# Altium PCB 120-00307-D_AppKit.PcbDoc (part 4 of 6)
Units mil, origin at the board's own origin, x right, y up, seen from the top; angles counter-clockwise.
Board outline 5150 x 3100 mil, 6 copper layers (L1, L2 (GND), L3-SIG, L4-SIG, L5 (PWR), L6), stack 61.956 mil thick; 413 components, 344 nets, 1685 pads, 1021 vias.
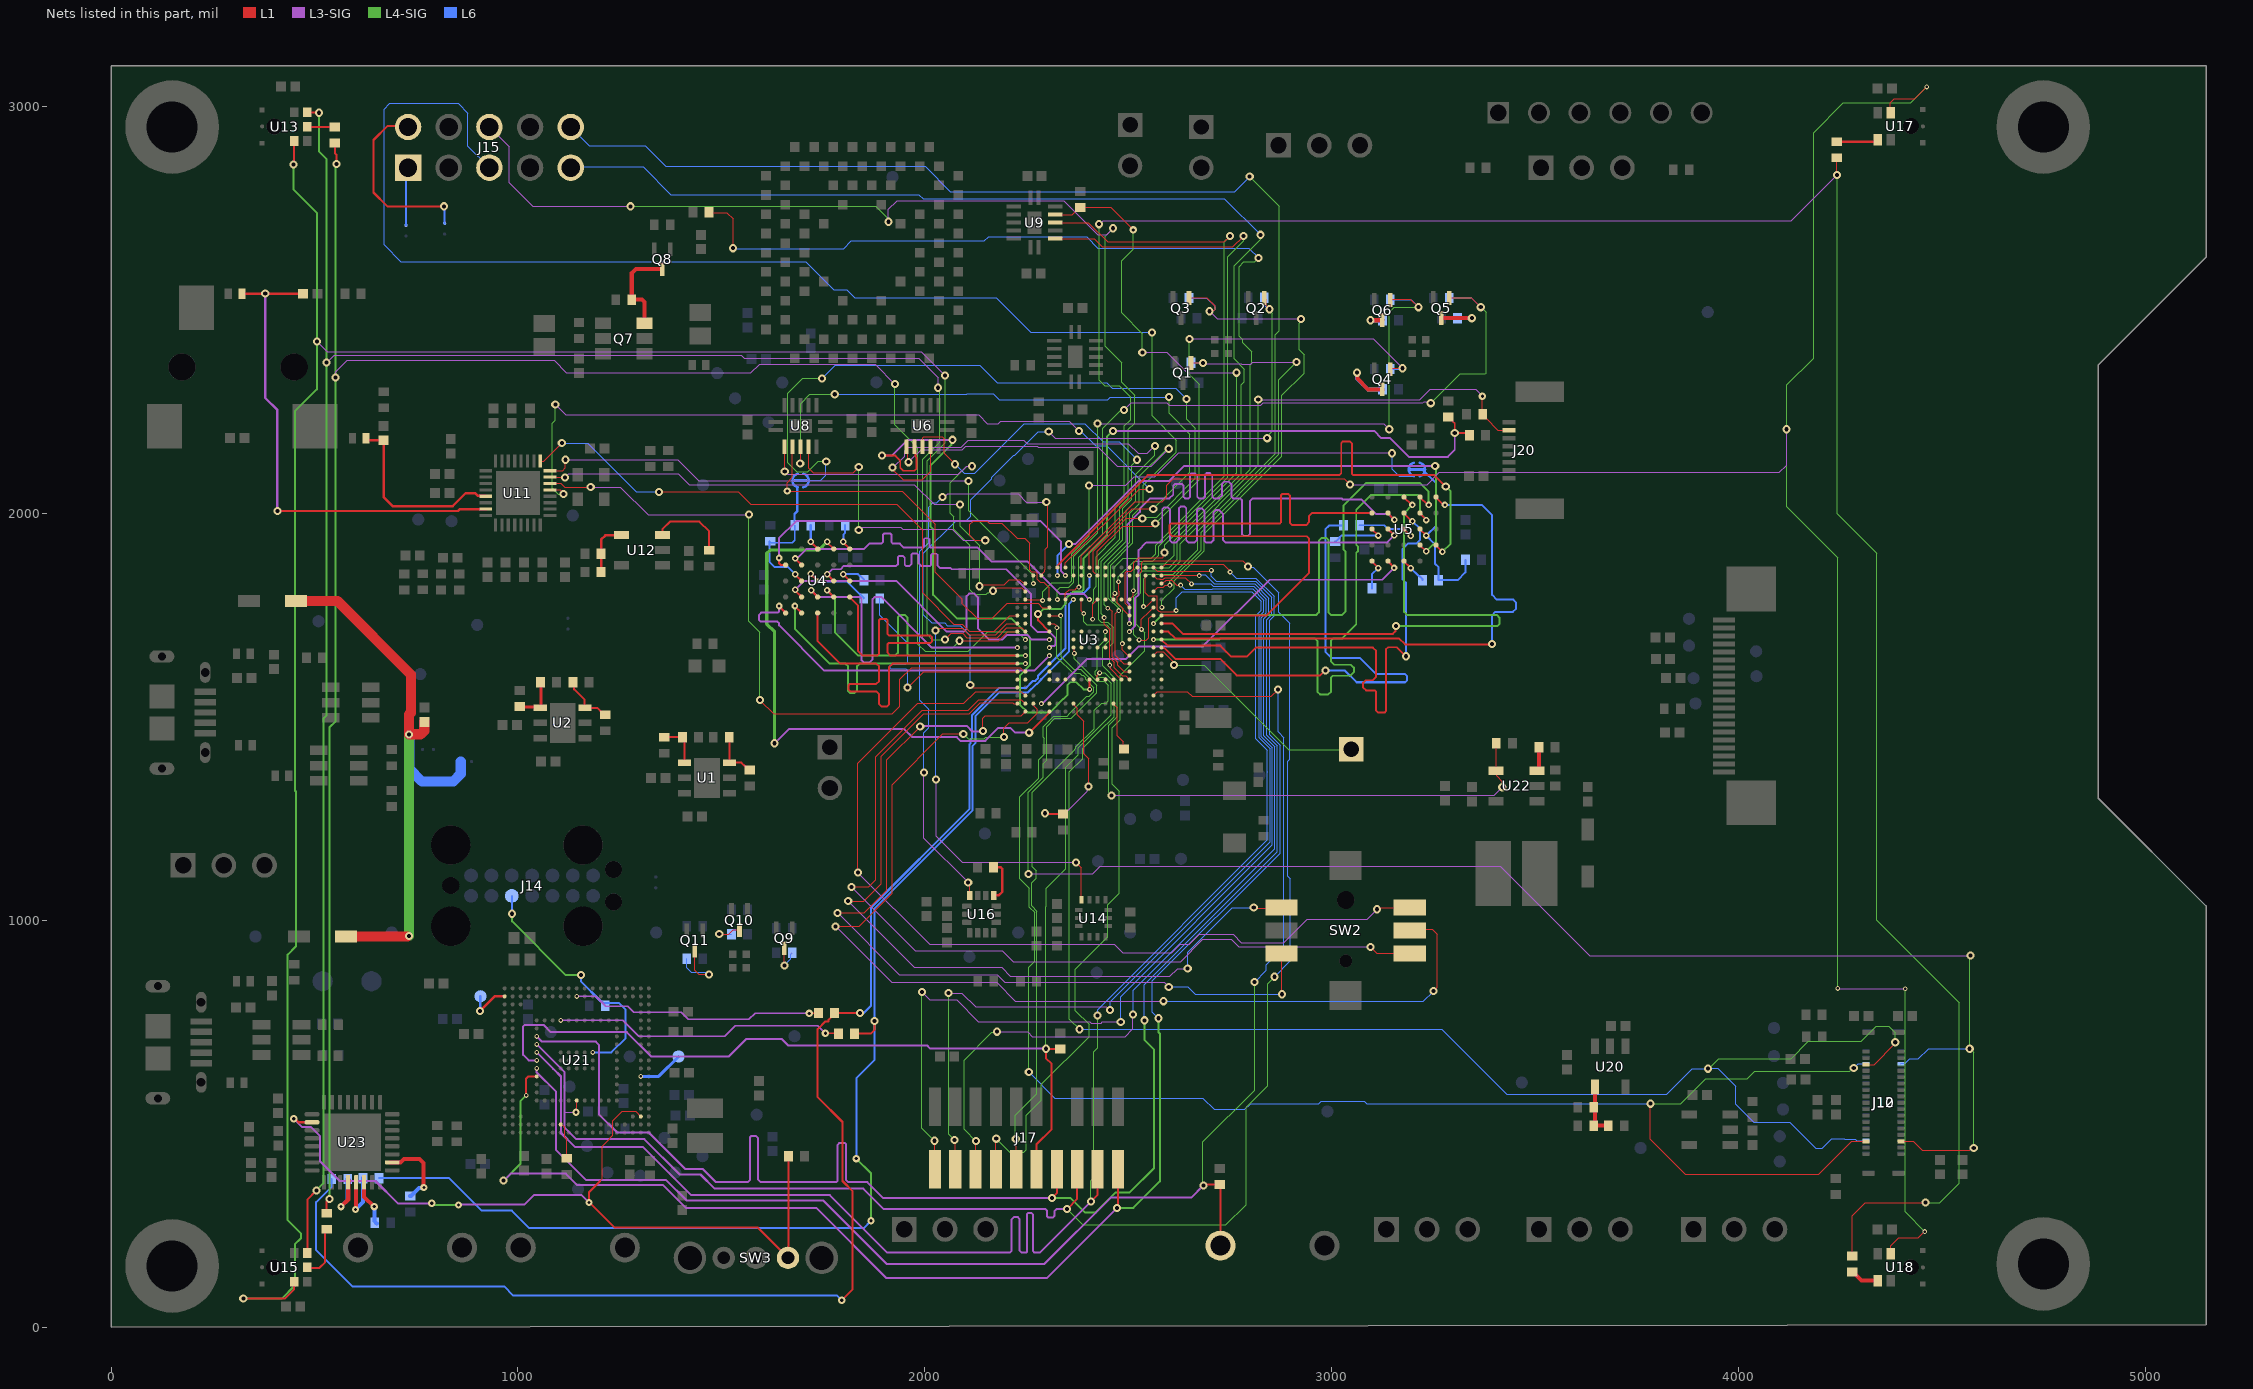
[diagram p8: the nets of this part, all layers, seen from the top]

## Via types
v1: diameter 20, hole 10, L1 to L6, tented both sides, 437 vias
v2: diameter 20, hole 10, L1 to L6, 330 vias
v3: diameter 12, hole 6, L1 to L6, tented both sides, 120 vias
v4: diameter 18, hole 8, L1 to L6, 93 vias
v5: diameter 16, hole 8, L1 to L6, tented both sides, 41 vias

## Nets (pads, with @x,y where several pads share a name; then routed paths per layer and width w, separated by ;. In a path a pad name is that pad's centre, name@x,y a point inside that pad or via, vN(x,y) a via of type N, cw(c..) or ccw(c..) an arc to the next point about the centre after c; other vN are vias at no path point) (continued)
NetQ4_3: Q4.3 R20.1 | length 176.5
  L1 w10: v2(3063,2346) 3063.68,2345.32 3063.68,2331.32 3090,2305 3124.09,2305 3125,2304.09 Q4.3@3125,2303
  L6 w10: v2(3063,2346) 3063,2332 3090,2305 R20.1@3125.63,2305
NetQ5_3: Q5.3 R21.2 | length 109.7
  L1 w10: Q5.3@3271,2479 3272,2480 v2(3345,2480)
  L6 w10: R21.2@3309.69,2480 v2(3345,2480)
NetQ6_3: Q6.3 R23.2 | length 59.3
  L1 w10: v2(3096,2475) Q6.3@3126,2475
  L6 w10: v2(3096,2475) R23.2@3125.31,2475
NetQ7_3: Q7.3 Q8.3 R43.1 | length 225.4
  L1 w10: R43.1@1280,2525 1280,2591 1290,2601 Q8.3@1353,2601 ; R43.1@1284,2526 1305,2526 1311.5,2519.5 Q7.3@1311.5,2467.4
NetQ9_3: Q9.3 R79.1 | length 81.4
  L1 w3: Q9.3@1654.68,930.85 1654.68,889.32 v2(1655,889)
  L6 w3: v2(1655,889) 1670.89,904.89 1670.89,916.94 R79.1@1674.37,920.43
NetQ10_3: Q10.3 R80.2 | length 84.1
  L1 w3: v2(1495,966) 1519,966 1529,976 1544.54,976 Q10.3@1544.68,975.85
  L6 w3: v2(1495,966) 1495.57,965.43 R80.2@1525,965.43
NetQ11_3: Q11.3 R82.2 | length 171.7
  L1 w3: Q11.3@1434.68,925.85 1434.68,876.92 1444.6,867 v2(1470,867)
  L6 w3: R82.2@1415.31,905.43 1415.31,883.69 1426.75,872.25 1460.15,872.25 1465.4,867 v2(1470,867)
NetR1_1: R1.1 R4.2 U1.4 | length 109.7
  L1 w5: R1.1@1360,1450 R4.2@1405,1450 1410,1445 U1.4@1410,1387.4
NetR3_2: R3.2 R6.2 U1.3 | length 108.7
  L1 w5: U1.3@1519.69,1387.4 R6.2@1519.69,1450 ; U1.3@1520,1387.4 1549.6,1387.4 1558.99,1378.01 1559.7,1378.01 1561,1376.72 R3.2@1561,1376
NetR7_1: R7.1 R10.2 U2.4 | length 117.4
  L1 w8: R7.1@1002,1524 1053.4,1524 U2.4@1055,1522.4 ; R10.2@1055.31,1585 1057,1583.31 1057,1524 U2.4@1057,1522
NetR9_2: R9.2 R11.2 U2.3 | length 122.2
  L1 w5: R11.2@1135.31,1585 1138.37,1581.95 1138.37,1567.63 1164,1542 U2.3@1164,1522.4 ; U2.3@1165,1522.4 1165.4,1522 1195,1522 1203.67,1513.33 1204.7,1513.33 1207,1511.03 R9.2@1207,1510
NetR27_1: R27.1 U4.C5 | length 80.8
  L1 w5: v5@1800,1850.3 U4.C5@1815.42,1834.89
  L6 w4.72: v5@1799,1851 1835.63,1851 1840.19,1846.44 1842.16,1846.44 1850.63,1837.97 R27.1@1850.63,1836
  other v5: 1800,1850.47
NetR29_1: R29.1 U5.C5 | length 135
  L1 w5: U5.C5@3099.35,1961.35 v5@3114.77,1945.93
  L6 w4.72: R29.1@3009,1930.68 3010.97,1930.68 3019.44,1939.15 3019.44,1941.12 3024.08,1945.77 v5(3114.77,1945.77)
NetR32_1: R32.1 U4.A3 | length 66.8
  L1 w5: v5(1720,1930.47) 1720,1929.74 U4.A3@1737.03,1912.71
  L6 w5: v5@1720,1929 v5(1720,1930.47) R32.1@1720,1971
NetR33_1: R33.1 U5.A3 | length 66.3
  L1 w5: U5.A3@3178.09,1882.61 v5@3194.77,1865.93
  L6 w5: v5(3194.77,1865.77) 3214.24,1846.3 3215.67,1846.3 3224,1837.97 R33.1@3224,1836
NetR34_2: R34.2 U4.C3 | length 183.6
  L1 w5: v5@1720,1851 U4.C3@1737.03,1833.97
  L6 w4.72: v5@1718,1854 1739,1833 1808.32,1833 1839.88,1801.44 1841.85,1801.44 1850.31,1792.97 R34.2@1850.31,1791
  other v5: 1720,1851.47
NetR35_2: R35.2 U5.C3 | length 160.4
  L1 w5: U5.C3@3178.15,1961.41 v5(3194.77,1944.77)
  L6 w4.72: R35.2@3068.69,1971 3129.63,1971 3139,1961.63 3177.9,1961.63 v5(3194.77,1944.77)
NetR36_2: R36.2 U3.V8 | length 403.4
  L1 w3: U3.V8@2365.63,1532.52 2365.63,1530.76 2369.05,1527.34 2369.05,1526.69 2375.13,1520.61 2375.13,1504.87 2391,1489 2391,1409.5 2403,1397.5 v2(2403,1329)
  L1 w5: v2(2296,1263) 2298,1261 R36.2@2340,1261
  L3-SIG w3: v2(2296,1263) 2346,1263 2400.25,1317.25 2400.25,1326.25 v2(2403,1329)
NetR37_1: R37.1 U3.V13 | length 121.4
  L1 w3: U3.V13@2464.05,1532.52 2474,1522.57 2474,1453 2488,1439 R37.1@2488,1421
NetR60_1: R60.1 U12.3 | length 196.1
  L1 w5: U12.3@1355,1944 1355.97,1944.97 1355.97,1961.97 1374,1980 1446,1980 1470,1956 R60.1@1470,1909.68
NetR61_2: R61.2 R62.1 U12.4 | length 133.3
  L1 w6: R62.1@1204.68,1856 1204.68,1935.68 1215,1946 U12.4@1254,1946
NetR64_1: R64.1 U13.8 | length 68
  L1 w5: U13.8@482.57,2951 483.89,2949.68 R64.1@550,2949.68
NetR65_1: R65.1 U15.8 | length 134.6
  L1 w5: U15.8@482.28,145.43 512.43,145.43 526,159 526,240 R65.1@529,243
NetR66_1: R66.1 U16.1 | length 111.3
  L1 w6: R66.1@2163,1131 2164,1130 R66.1@2169.37,1130 2187,1130 2191,1126 2191,1070 2181.9,1060.9 2169.56,1060.9 U16.1@2169.53,1060.87
NetR67_1: R67.1 U17.1 | length 95.1
  L1 w6: R67.1@4250,2914 4336.64,2914 U17.1@4342.64,2920
NetR68_1: R68.1 U18.1 | length 67.9
  L1 w10: R68.1@4283,133.97 R68.1@4287.8,129.17 ; R68.1@4287.83,129.17 4302.98,114.02 U18.1@4342.64,114.02
NetR70_2: R70.2 R73.2 R74.1 U20.4 | length 131.1
  L1 w10: R74.1@3644.69,495 R74.1@3647.6,495 ; R74.1@3647,494 3647.6,494.6 R74.1@3647.6,495 ; U20.4@3647.6,589.75 R74.1@3647.6,495 ; R73.2@3679,493 3677,495 R74.1@3647.6,495
NetR76_2: R76.2 U21.V8 | length 90.9
  L1 w3: U21.V8@1105.32,497.84 1107.17,497.84 1109.4,495.6 1110.4,495.6 1115,491 1115,466 1120,461 R76.2@1120,414.69
NetR87_2: R87.2 U22.3 | length 52.4
  L1 w10: U22.3@3509,1373 3510,1374 R87.2@3510,1425
NetR105_2: R105.2 U23.30 | length 120
  L1 w10: U23.30@621.96,361.59 621.96,320.04 646,296 v4(647,296)
  L6 w10: v4(647,296) 647.66,295.34 647.66,260.34 R105.2@653,255
NetR106_2: R106.2 U23.2 | length 194.6
  L1 w10: U23.2@685,404.94 711.94,404.94 720,413 758,413 768,403 768,344 v4(769,343)
  L6 w10: R106.2@735,322 736.97,322 756.44,341.47 768.47,341.47 v4@770,343
NetR107_2: R107.2 U23.28 | length 149.4
  L1 w10: v4(565,296) 583,314 U23.28@583,363
  L6 w10: v4(565,296) 581.69,312.69 R107.2@581.69,364
NetR108_2: R108.2 U23.29 | length 156.7
  L1 w10: v4@601,290 601.98,290.98 601.98,361.3 U23.29@602.27,361.59
  L6 w10: v4(601,289) 619.31,307.31 R108.2@619.31,366
NetR109_1: R109.1 U21.B10 | length 624.8
  L1 w3.2: v4(1716,771) 1738.31,771 R109.1@1739.32,772
  L3-SIG w3.2: v3(1144.68,812.8) 1191.89,812.8 1216.62,788.07 1269.93,788.07 1284.57,773.42 1401.57,773.42 1419,756 1568,756 1583,771 v4(1716,771)
NetR110_1: R110.1 U21.E8 | length 718.1
  L1 w3.2: v4(1756,722) 1787.32,722 R110.1@1788.32,721
  L3-SIG w3.2: v3(1105.32,753.74) 1258.26,753.74 1297,715 1508,715 1534,741 1737,741 v4(1756,722)
NetTP46_1: TP46.1 U21.B1 | length 111.8
  L1 w6: v1(907,777) 942.8,812.8 U21.B1@967.52,812.8
  L6 w6: v1(907,777) 907,812 TP46.1@908,813
NSRST: J17.10 R85.1 U3.J12 U21.K5 | length 2936.3
  L1 w5: J17.10@2275,388.23 2275,449 2312,486 2312,647 2298,661 v2(2298,684) 2298.68,683.32 R85.1@2333,683.32
  L3-SIG w5: v3(1046.26,655.32) 1026.57,655.32 1013,668.89 1013,739 1017,743 1063,743 1081,725 1268,725 1328,665 1518,665 1561,708 1649,708 1665,692 2006,692 2013,685 2297,685 v2(2298,684)
  L4-SIG w3: v2@2297,686 2298,687 2298,1033.49 2298.5,1033.99 2298.5,1078.5 2347,1127 2347,1376 2378,1407 2378,1424 2459,1505 2459,1582 2444,1597 2426,1597 2419,1604 2419,1611.85 2424.68,1617.53 2424.68,1670.32 2444.37,1690 v3(2444.37,1709.68)
NSRST_J: J14.12 R94.1 U21.J12 | length 606.7
  L4-SIG w5: v2(986,1016) 986,997 1118,865 v2(1155,865)
  L6 w5: J14.12@985,1060 985,1017 v2(986,1016) ; v2(1155,865) 1155,849.69 1204.39,800.3 1206.36,800.3 1210.52,796.13 1248.87,796.13 1265,780 1265,710 1230,675 v3(1184.05,675)
OSPI0_D0: U3.K19 U5.D3 | length 1396.2
  L1 w4.72: U3.K19@2582.16,1690 2597.26,1674.91 2726.99,1674.91 2753.9,1648 2792,1648 2814,1670 3102,1670 3110,1662 3110,1598 3102,1590 3084,1590 3078,1584 3078,1572 3085,1565 3107,1565 3110,1562 3110,1515 3114,1511 3131.23,1511 3134,1513.76 3134,1666 3139,1671 3161,1671 v2(3183,1649)
  L1 w5: U5.D3@3178.06,2000.69 3197.75,1981 v5(3199,1981)
  L6 w4.72: v2(3183,1649) 3183,1830 3175,1838 3175,1913 3188,1926 3209,1926 3218,1935 3218,1962 v5(3199,1981)
OSPI0_D1: U3.K18 U5.D2 | length 1414.3
  L1 w5: U5.D2@3217.09,2000.35 v5@3232.77,1984.67
  L4-SIG w4.72: v3(2562.48,1690) 2723.81,1690 2726.81,1693 2959,1693 2966,1686 2966,1561 2972,1555 2992,1555 2999,1562 2999,1597 3003,1601 3046,1601 3055,1610 3055,1621 3048,1628 3007,1628 2999,1636 2999,1688 3004,1693 3027,1693 3061,1727 3061,1902.78 3064.86,1906.64 3064.86,1919.36 3061,1923.22 3061,2009 3097,2045 3212.62,2045 3217.5,2040.13 3217.5,2001.24 3232.77,1985.97 v5(3232.77,1983.77)
OSPI0_D2: U3.J15 U5.C4 | length 1497.5
  L1 w5: U5.C4@3139,1961.63 3154.55,1946.08 v5(3154.55,1945.79)
  L3-SIG w4.72: v3(2503.43,1709.68) 2517,1723.26 2517,1791 2526,1800 2526,1910 2544,1928 ; 2544.76,1929 2580,1929 2584,1933 2584,2010 2589,2015 2598,2015 2603,2010 2603,1934 2608,1929 2618,1929 2625,1936 2625,2013 2629,2017 2639,2017 2643,2013 2643,1934 2648,1929 2664,1929 2669,1934 2669,2008 2673,2012 2682,2012 2688,2006 2688,1932 2691,1929 2705,1929 2710,1934 2710,2002 2716,2008 2724,2008 2733,1999 2733,1935 2739,1929 3137.76,1929 v5(3154.55,1945.79)
OSPI0_D3: U3.H15 U5.D4 | length 1505
  L1 w5: U5.D4@3138.78,2000.78 v5(3154.77,1984.77)
  L3-SIG w4.72: v3(2503.43,1729.37) 2503.43,1776.57 2498,1782 2498,1972.72 2529,2003.72 2529,2012 2554,2037 2601.5,2037 2611,2046.5 2611,2068 2615,2072 2633,2072 2636,2069 2636,2041 2640,2037 2649,2037 2652,2040 2652,2095.24 2654.77,2098 2665,2098 2670,2093 2670,2041 2674,2037 2686,2037 2689,2040 2689,2095 2693,2099 2701,2099 2707,2093 2707,2041 2711,2037 2723.3,2037 2731,2044.7 2731,2073 2736,2078 2748,2078 2754,2072 2754,2041 2758,2037 2776,2037 2780,2033 2780,1949 2784,1945 2795,1945 2800,1950 2800,2031 2806,2037 3025,2037 3028,2034 3074.13,2034 3110,1998.13 3141.41,1998.13 v5(3154.77,1984.77)
OSPI0_D4: U3.G19 U5.D5 | length 1519.2
  L1 w4.72: U3.G19@2582.16,1749.05 2840.06,1749.05 2945,1854 2945,1938 2939,1944 2608.5,1944 ; 2608.5,1944.5 2606.52,1946.48 2601.5,1951.5 2601.5,1970.5 2606.5,1975.5 2873.23,1975.5 2876,1978.26 2876,2045 2879,2048 2894,2048 2898,2044 2898,1977.5 2904,1971.5 2937.5,1971.5 2945,1979 2945,1994 2952,2001 U5.D5@3099.63,2001
OSPI0_D5: U3.H19 U5.E3 | length 1414.4
  L1 w4.72: U3.H19@2582.16,1729.37 2609.63,1729.37 2635,1704 3151,1704 3157.14,1710.14 3157.14,1721.14 v2(3159,1723)
  L1 w5: U5.E3@3178.22,2040.22 3197.44,2021 v5(3199,2021)
  L4-SIG w4.72: v2(3159,1723) 3408,1723 3413,1728 3413,1744 3407,1750 3186.37,1750 3178.37,1758 3178.37,2000.37 v5(3199,2021)
OSPI0_D6: U3.H18 U5.E2 | length 1414.4
  L1 w5: U5.E2@3217.5,2040.13 3236.62,2021 v5(3239,2021)
  L4-SIG w4.72: v3(2562.48,1729.37) 2583.11,1750 2962,1750 2969,1757 2969,1933 2976,1940 2987,1940 2993,1934 2993,1756 2999,1750 3025,1750 3035,1760 3035,1905.78 3029.31,1911.46 3029.31,2018.32 3086,2075 3217,2075 3239,2053 v5(3239,2021)
OSPI0_D7: U3.J19 U5.E1 | length 1397
  L1 w4.72: U3.J19@2582.16,1709.68 2599.32,1709.68 2616,1693 3166,1693 3181,1678 3394,1678 v2(3395,1679)
  L1 w5: U5.E1@3256.77,2040.03 3273.7,2023.1 3276.9,2023.1 v5(3279,2021)
  L6 w4.72: v5(3279,2021) 3369,2021 3395,1995 3395,1799.56 3406.56,1788 3447,1788 3454,1781 3454,1766 3446,1758 3403,1758 3395,1750 v2(3395,1679)
OSPI0_INTn: R30.1 U5.A5 | length 78.4
  L1 w5: U5.A5@3099.03,1882.29 v5@3114.77,1866.56
  L6 w4.72: R30.1@3099.31,1816 3099.31,1850.32 v5(3114.77,1865.77)
OSPI0_RESETn: U3.V4 U5.A4 | length 1028.3
  L1 w5: U5.A4@3138.89,1882.79 3138.89,1882.05 3154,1866.94 v5(3154,1866)
  L3-SIG w4.72: v3(2286.89,1532.52) 2288.86,1532.52 2292.07,1535.73 2292.73,1535.73 2399,1642 2494.8,1642 2525.8,1673 2684,1673 2848,1837 3125,1837 v5(3154,1866)
OSPI0_RXDS: R35.1 U3.L19 | length 1235.8
  L1 w5: U3.L19@2582.16,1670.32 2582.69,1669.79 2589.21,1669.79 2616.5,1642.5 2726.5,1642.5 2767,1602 2972,1602 2984,1614 v2(2985,1614)
  L6 w5: v2(2985,1614) 3033,1614 3062,1585 3181,1585 3186,1590 3186,1600 3181,1605 3110,1605 3070,1645 3000,1645 2985,1660 2985,1961 2994,1970 R35.1@3029,1970
OSPI0_SCLK: U3.B6 U5.B2 | length 1311.7
  L1 w5: U5.B2@3217.52,1922.04 v5(3232.77,1906.77)
  L3-SIG w4.72: v2(2355,1925) 2371,1925 2526,2080 2601.72,2080 2638.72,2117 v2(3255,2117)
  L4-SIG w4.72: v5(3232.77,1906.77) 3257.11,1931.11 3257.11,2114.89 v2(3255,2117)
  L6 w4.72: v3(2326.26,1847.48) 2326.26,1896.26 v2(2355,1925)
OSPI0_SCLKN: U3.A6 U5.B1 | length 1414.9
  L1 w4.72: U3.A6@2326.26,1867.16 2327.24,1868.15 2327.24,1873.24 2548,2094 3019,2094 3024,2099 3024,2173 3028,2177 3041,2177 3041.05,2177.05 3044.95,2177.05 3050,2172 3050,2098 3054,2094 3253,2094 v2(3281,2066)
  L1 w5: U5.B1@3256.8,1921.95 v5@3272.77,1905.99
  L4-SIG w4.72: v5(3272.77,1905.77) 3293,1926 3293,2054 v2(3281,2066)
OSPI0_SS0: R31.2 R33.2 S6.1 U5.C2 | length 435.1
  L1 w5: U5.C2@3217.43,1961.32 v5@3232.77,1945.99
  L6 w4.72: R33.2@3263.37,1836 3310,1836 3329.31,1855.31 R31.2@3329.31,1886
  L6 w5: S6.1@3223.3,2108 3257.11,2074.19 3257.11,1970.11 v5(3232.77,1945.77) 3254,1924.53 3254,1877 3263.37,1867.63 R33.2@3263.37,1836
OSPI1_D0: U3.L1 U4.D3 | length 898
  L1 w5: v5(1721,1811.47) 1721,1810.63 U4.D3@1737.03,1794.6
  L3-SIG w4.72: v5(1721,1811.47) 1721,1810.63 1737.03,1794.6 1840,1794.6 ; 1840,1795 1845,1790 1845,1639 1850,1634 1865,1634 1872,1641 1872,1789.6 1877,1794.6 1893.4,1794.6 2017.68,1670.32 v3(2227.84,1670.32)
OSPI1_D1: U3.K5 U4.D2 | length 896.6
  L1 w5: v5(1682,1812.47) 1682,1810.26 U4.D2@1697.66,1794.6
  L3-SIG w4.72: v5(1682,1812.47) 1703.53,1834 1930,1834 2054.32,1709.68 2096,1709.68 ; 2096,1709 2103,1716 2103,1797 2109,1803 2122,1803 2131,1794 2131,1717.68 2158.68,1690 2191.24,1690 2202.6,1701.36 2252.23,1701.36 2263.59,1690 v3(2306.57,1690)
OSPI1_D2: U3.L5 U4.C4 | length 890.6
  L1 w5: v5@1760.22,1850.15 U4.C4@1776.4,1833.97
  L3-SIG w4.72: v5(1760.22,1850.44) 1772.62,1862.84 1793.48,1862.84 1801.64,1871 1930,1871 1934,1875 1934,1892.24 1936.76,1895 1947,1895 1951,1891 1951,1874 1954,1871 1963,1871 1968,1876 1968,1899.24 1970.76,1902 1980,1902 1985,1897 1985,1877 1991,1871 2013.24,1871 2016,1873.76 2016,1898 2019,1901 2029,1901 2032,1898 2032,1871.36 2037,1866.36 2063.36,1866.36 2066.88,1862.84 2200.16,1862.84 2260.99,1802.01 2260.99,1725.01 2276.95,1709.05 2305.95,1709.05 2321,1694 2321,1676.6 2318.24,1673.83 2312.06,1673.83 2308.55,1670.32 v3(2306.57,1670.32)
OSPI1_D3: U3.M2 U4.D4 | length 812.9
  L1 w5: v5@1760,1811.43 U4.D4@1775.98,1795.45
  L4-SIG w4.72: v5(1760,1811.47) 1780,1791.47 1780,1707 1836.37,1650.63 1928,1650.63 ; 1928,1651 1934,1657 1934,1745 1939,1750 1952,1750 1958,1744 1958,1653.63 1961,1650.63 v3(2247.52,1650.63)
OSPI1_D4: U3.M1 U4.D5 | length 916.2
  L1 w4.2: U4.D5@1815.77,1794.6 U4.D5@1817.45,1792.92
  L1 w4.72: U4.D5@1817.45,1792.92 1836,1774.37 1836,1663 1848.37,1650.63 1884,1650.63 ; 1884,1651 1888,1655 1888,1738 1891,1741 1905,1741 1909,1737 1909,1703 1912,1700 2014,1700 2018,1696 2018,1685 2015,1682 ; 2014,1682 1912,1682 1909,1679 1909,1657.63 1916,1650.63 U3.M1@2227.84,1650.63
OSPI1_D5: U3.N1 U4.E3 | length 916.7
  L1 w4.72: U4.E3@1737.03,1755.23 1737.03,1685.97 1792.05,1630.95 1881,1630.95 ; 1881,1631 1888,1624 1888,1588 1881,1581 1816,1581 1813,1578 1813,1567 1818,1562 1882,1562 1888,1556 1888,1531 1894,1525 1907,1525 1912,1530 1912,1621.95 1921,1630.95 U3.N1@2227.84,1630.95
OSPI1_D6: U3.N2 U4.E2 | length 812.3
  L1 w5: v5(1681,1772.47) 1681,1771.89 U4.E2@1697.66,1755.23
  L4-SIG w4.72: v5(1681,1772.47) 1681,1717 1767.05,1630.95 1805.05,1630.95 ; 1805,1631 1805.05,1630.95 ; v3(2247.52,1630.95) 1840,1630.95 1834,1624.95 1834,1565 1828,1559 1816,1559 1812,1563 1812,1624 1805.05,1630.95
OSPI1_D7: U3.M5 U4.E1 | length 886.3
  L1 w5: v5(1642,1772.47) 1642,1771.52 U4.E1@1658.29,1755.23
  L3-SIG w4.72: v5(1642,1772.47) 1642,1758.76 1639.24,1756 1598,1756 1593,1751 1593,1738 1597,1734 1638,1734 1642,1730 1642,1725 1753.47,1613.53 2269.48,1613.53 v3(2306.57,1650.63)
OSPI1_INTn: R28.1 U4.A5 | length 67.2
  L1 w5: v5(1800,1930.47) 1800,1928.48 U4.A5@1815.77,1912.71
  L6 w5: v5@1800,1930 v5(1800,1930.47) 1800,1948 1804.68,1952.68 R28.1@1804.68,1971
OSPI1_RESETn: U3.W5 U4.A4 | length 1402.2
  L1 w5: v5(1760.77,1930.23) 1760.77,1928.34 U4.A4@1776.4,1912.71 ; v2(2257,1461) 2306.22,1510.22 U3.W5@2306.22,1512.48
  L1 w8: U3.W5@2306.22,1512.48 U3.W5@2306.57,1512.84
  L3-SIG w5: v2(1631,1435) 1666,1470 1950,1470 1970,1450 2078.96,1450 2087.96,1441 2149,1441 2180,1472 2211.38,1472 2222.38,1461 v2(2257,1461)
  L4-SIG w8: v2(1631,1435) 1631,1709 1612,1728 1612,1902 1620,1910 1740,1910 v5@1761,1931
OSPI1_RXDS: R34.1 U3.P1 | length 610
  L1 w3: v2(1958,1572) 1997.26,1611.26 U3.P1@2227.84,1611.26
  L6 w3: R34.1@1889.68,1791 1889.68,1749.32 1958,1681 1958,1634 1955,1631 1919,1631 1916,1628 1916,1619.76 1917.76,1618 ; 1918,1618 1953.53,1618 1958,1613.53 v2(1958,1572)
OSPI1_SCLK: U3.E10 U4.B2 | length 897.2
  L1 w5: v5@1682,1889 U4.B2@1697.66,1873.34
  L3-SIG w4.72: v5(1682,1889.47) 1685.05,1889.47 1688.76,1893.18 1690.18,1893.18 1710,1913 1851,1913 1864,1926 1893,1926 1898,1931 1898,1947.76 1901,1950.76 1915.24,1950.76 1918,1948 1918,1930 1922,1926 1939,1926 1949,1916 1995,1916 1998,1919 1998,1936 2001,1939 2009.24,1939 2012,1936.24 2012,1919 2015,1916 2130,1916 2164,1882 2252.37,1882 2332.87,1801.5 2391.93,1801.5 v3(2405,1788.43)
OSPI1_SCLKN: U3.B7 U4.B1 | length 898.1
  L1 w5: v5@1641.78,1890.25 1641.78,1878.27 1646.71,1873.34 U4.B1@1658.29,1873.34
  L3-SIG w4.72: v5@1641.78,1890.68 1641.78,1938.64 1684.33,1981.18 2285.32,1981.18 2335.6,1930.91 2335.6,1857.83 v3@2345.73,1847.7
  other v3: 2345.95,1847.48
  other v5: 1642,1890.47
OSPI1_SS0: R26.2 R32.2 S5.1 U4.C2 | length 337.3
  L1 w5: v5(1682,1850.47) 1682,1849.63 U4.C2@1697.66,1833.97
  L6 w4.72: R26.2@1618,1928 1674,1928 1680.63,1934.63 R32.2@1680.63,1971
  L6 w5: R26.2@1618,1931 1618,1928 1618,1881 1631,1868 1664.47,1868 v5(1682,1850.47)
  L6 w6: R32.2@1680,1980 1680,1999 1687,2006 1687,2063
P0_0: U3.R19
P0_1: U3.R13
P0_2: U3.R12
P0_3: J10.32 J12.32 U3.R11 | length 3747.2
  L1 w3: U3.R11@2424.68,1591.57 2424.68,1601.74 2430,1607.06 v3(2430,1608) ; J10.32@4314.17,645.24 4334.24,645.24 4386,697 v2(4386,700)
  L4-SIG w3: v2(2381,732) 2356,757 2356,1365 2388,1397 2388,1422.51 2429.74,1464.25 2466,1500.49 2466,1585 2443,1608 v3(2430,1608) ; v2@3926,634 3952,660 4130,660 4172,702 4302,702 4339,739 4370,739 4386,723 v2(4386,700)
  L6 w3: v2(2381,732) 3271,732 3431,572 3824,572 3887,635 v2@3925,635 ; v2@3925,636 3950,636 3994,592 3994,548 4038,504 4126,504 4191,439 4206,439 4230,463 4260.5,463 4261.5,462 4288,462 4291.5,458.5 J12.32@4314.17,458.5
  other v2: 3926,635
P0_4: U3.R10 U6.3 | length 1471
  L1 w4.72: v2(1895,2142) 1928,2142 1940,2130 1940,2112 1947,2105 1975,2105 1980,2110 1980,2137 1977,2140 1977,2154 U6.3@1976,2155 ; v2@2065.59,2181 v2(2068,2181) ; U3.R10@2405,1591.57 2405,1568 v3(2405.5,1567.5)
  L3-SIG w4.72: v2(1895,2142) 1919,2142 1958,2181 v2(2068,2181)
  L4-SIG w4.72: v2(2068,2181) 2065.64,2178.64 2065.64,2168.64 2014,2117 2014,1968 2021,1961 2021,1800 2079,1742 2213,1742 2253,1702 2253,1700.59 2258.88,1694.71 2258.88,1626.24 2234,1601.36 2234,1530 2253,1511 2308.36,1511 2341.24,1543.88 2341.88,1543.88 2351,1553 2351,1578 2358,1585 2373,1585 2390.5,1567.5 v3(2405.5,1567.5)
P0_5: U3.N15 U6.2 | length 1366.6
  L1 w3: U6.2@1955.63,2163.82 1958.85,2160.59 1958.85,2126.15 v2@1961,2124 ; v3(2477,1761) 2476,1761 2468,1753 2468,1652 2489.05,1630.95 U3.N15@2503.43,1630.95
  L3-SIG w3: v2(1960,2126) 1991,2157 2092.49,2157 2100.49,2165 2277,2165 2279,2163 2427,2163 2474,2116 2557,2116 v2(2600,2159)
  L4-SIG w3: v3(2477,1761) 2475.28,1762.72 2475.28,1767.72 2451,1792 2451,1876 2504,1929 2504,2000 2528,2024 2528,2091 2596,2159 v2(2600,2159)
P0_6: U3.P15 U6.5 | length 1516.8
  L1 w3: v2@1916,2116 1916,2114 1947,2083 1994,2083 2015,2104 U6.5@2015,2156 ; v3(2450,1767) 2452.44,1767 2454.44,1765 2455,1765 2461,1759 2461,1647.49 2472,1636.49 2472,1636 2475,1633 2475,1627 2490.74,1611.26 U3.P15@2503.43,1611.26
  L3-SIG w3: v2(1921,2113) 1923,2113 1951,2141 1951,2154 1960,2163 2090,2163 2107,2180 2243,2180 2252,2171 2501,2171 2524.5,2147.5 2547.5,2147.5 v2(2566,2166)
  L4-SIG w3: v3(2450,1767) 2442,1775 2442,1878 2496,1932 2496,2008 2519,2031 2519,2096 2566,2143 v2(2566,2166)
P0_7: U3.R15 U6.4 | length 1307.5
  L1 w3: U6.4@1995,2163.82 1995,2186 1998,2189 2043,2189 2048,2184 2048,2148 v2(2075,2121) v2@2075,2120 ; v3(2441,1744) 2441,1727.9 2454.87,1714.03 2454.87,1645.13 2466,1634 2466,1621 2486,1601 2494,1601 U3.R15@2503.43,1591.57
  L4-SIG w3: v3(2441,1744) 2441,1746.44 2438.08,1749.36 2438.08,1749.92 2434,1754 2434,1882 2487,1935 2487,2013 2509,2035 2509,2119 v2(2522,2132)
  L6 w3: v2(2075,2121) 2097,2099 2123,2099 2245,2221 2394,2221 2439,2176 2478,2176 v2(2522,2132)
P1_0: J15.6 U3.R14 | length 2994.8
  L1 w3: v3(2455,1627) 2456.08,1625.92 2456.08,1619.23 U3.R14@2483.74,1591.57
  L3-SIG w3: J15.6@928,2955 928,2952 J15.6@930,2950 979,2901 979,2813 1037,2755 v2(1277,2755) ; v2(1911,2717) 1911,2748 1932,2769 2342,2769 2426,2685 2447,2685 v2(2463,2701)
  L4-SIG w3: v2(1277,2755) 1880,2755 1907.75,2727.25 1907.75,2720.25 v2(1911,2717) ; v3(2455,1627) 2455,1674 2463,1682 2463,1720 2450,1733 2434,1733 2428,1739 2428,1885 2480,1937 2480,2016 2501,2037 2501,2207 2516,2222 2516,2291 2484,2323 2484,2371 2444,2411 2444,2682 v2(2463,2701)
P1_1: J15.5 U3.M15 | length 3600.3
  L1 w3: v3(2486,1680) 2486,1665 2499.06,1651.94 2502.12,1651.94 U3.M15@2503.43,1650.63
  L4-SIG w3: v3(2486,1680) 2486,1755.15 2487.5,1756.65 2487.5,1765.35 2481.35,1771.5 2479.99,1771.5 2457,1794.49 2457,1873 2512,1928 2512,1996 2537,2021 2537,2069 2619,2151 2619,2180 2559,2240 v2(2559,2445)
  L6 w3: J15.5@928,2847 928,2852 877,2903 877,2984 853,3008 685,3008 671,2994 671,2660 712,2619 1707.94,2619 1776.94,2550 1808,2550 1828,2530 2176,2530 2261,2445 v2(2559,2445)
P1_2: U3.L15
P1_3: U3.K15
P1_4: U3.M19
P1_5: U3.L18
P1_7: U3.J18
P3_2: S6.2 U3.E2 | length 1279.9
  L1 w3: U3.E2@2247.52,1788.43 2285.14,1788.43 2287.56,1786 v3(2290,1786)
  L3-SIG w3: v2(2404,2069) 2494,2069 2515,2090 2566,2090 2625,2149 3148,2149 v2(3149,2148)
  L4-SIG w3: v3(2290,1786) 2290,1808 2312,1830 2357,1830 2361,1834 2361,1901 2405,1945 2405,2068 v2(2404,2069)
  L6 w3: v2(3149,2148) 3149,2109 3166.95,2091.05 3202.98,2091.05
P3_3: U3.G2
P3_6: U3.V5
P3_7: J17.12 U3.L8 | length 1448
  L1 w3: v2(2224,462) 2225,461 J17.12@2225,388.23 ; U3.L8@2365.63,1670.32 2365.63,1668.46 2368,1666.09 v3(2368,1656)
  L4-SIG w3: v2(2224,462) 2223,463 2223,520 2276,573 2276,1022 2263,1035 2263,1092 2274,1103 2274,1122 2265,1131 2265,1315 2369,1419 2369,1420 2372,1423 2372,1426.49 2416.5,1470.99 2416.5,1515.65 2434.85,1534 2446,1534 2451,1539 2451,1578 2441,1588 2423,1588 2368,1643 v3(2368,1656)
P4_0: J17.14 J20.7 R90.2 U3.F18 | length 3103.2
  L1 w3: J17.14@2175,388.23 2175,465 v2@2178,468 ; v3(2533,1715) 2533,1740 2553,1760 2553.74,1760 U3.F18@2562.48,1768.74 ; R90.2@3371.69,2244 3371,2244.69 v4(3371,2288) v4@3372,2289 ; R90.2@3378,2235 3378.72,2235 3409.2,2204.51 J20.7@3436.21,2204.51
  L3-SIG w3: v2(2820,2280) 3217.51,2280 3242.51,2305 3355,2305 3371,2289 v4(3371,2288)
  L4-SIG w3: v2(2176,463) 2209,430 2244,430 2250,436 2250,521 2287,558 2287,597 2404,714 2404,744 2370,778 2370,880 2450,960 2450,1038 2478,1066 2478,1317 2461,1334 2461,1473 2481,1493 2481,1602 2541,1662 2541,1707 v3(2533,1715) 2520,1728 2520,1793.51 2531,1804.51 2531,1854 2536,1859 2605,1859 2628,1882 2628,1926 2820,2118 v2(2820,2280)
P4_1: J17.16 U3.B19 | length 2248.9
  L1 w3: J17.16@2125,388.23 2125,458 v2@2127,460 ; U3.B19@2582.16,1847.48 2582.65,1847.97 2589,1847.97 ; 2589.03,1848 2674.24,1848 v3(2675,1847.24)
  L3-SIG w3: v2(2178,726) 2253,726 2265,714 2493,714 2512,733 v2(2512,768)
  L4-SIG w3: v2(2126,457) 2097,486 2097,656 2165.26,724.26 2176.26,724.26 v2(2178,726)
  L6 w3: v2(2512,768) 2513,769 2513,828 2861,1176 2861,1426.49 2834,1453.49 2834,1741 2846,1753 2846,1792 2811,1827 2712,1827 2690,1849 2681.26,1849 ; v3(2675,1847.24) 2676.72,1848.97 2681.22,1848.97
P4_2: J17.18 U3.C19 | length 2322.1
  L1 w3: v2@2071,464 2075,460 J17.18@2075,388.23 ; U3.C19@2582.16,1827.8 2583.47,1829.1 2587.1,1829.1 2594,1836 2608,1836 2620.26,1823.74 2628.74,1823.74 v3(2629,1824)
  L3-SIG w3: v2(2059,821) 2091,821 2125,787 2445.98,787 2453.98,779 v2(2456,779)
  L4-SIG w3: v2(2059,821) 2059,474 v2(2073,460)
  L6 w3: v2(2456,779) 2456,800 2849,1193 2849,1421 2822,1448 2822,1746 2834,1758 2834,1787 2806,1815 2708,1815 2707,1814 2639,1814 v3(2629,1824)
P4_3: J17.20 U3.B18 | length 2486.2
  L1 w3: v2(2024,458) 2025,457 J17.20@2025,388.23 ; U3.B18@2562.48,1847.48 2571,1839 2577.32,1839 2578.32,1838 2585,1838 2585.06,1838.06 2586.07,1838.06 2589.01,1841 2590.51,1841 2591.51,1842 2641,1842 v3(2656,1827)
  L3-SIG w3: v2(1993,824) 2013,804 2079,804 2132,751 2406,751 2410,747 2434,747 2437,750 v2(2482,750)
  L4-SIG w3: v2(1993,824) 1993,489 v2(2024,458)
  L6 w3: v2(2482,750) 2482,812 2855,1185 2855,1424 2828,1451 2828,1743.51 2840,1755.51 2840,1789.49 2808.49,1821 2709.51,1821 2703.51,1827 v3(2656,1827)
P4_4: J17.4 U3.B17 U21.J5 | length 4213.4
  L1 w3: U3.B17@2542.8,1847.48 2542.8,1805.2 2550,1798 2570,1798 2570.99,1797.01 2572,1796 2572,1763 2576,1759 2578.15,1759 2578.65,1758.5 2612.7,1758.5
  L1 w5: v2(2409,309) 2425,325 J17.4@2425,388.23
  L3-SIG w5: v3(1046.26,675) 1086.76,634.5 1087.42,634.5 1106,615.92 1106,477 1140,443 1307,443 1426,324 1767,324 1908,183 2209,183 2214,188 2214,264.73 2219.27,270 2229,270 2233,266 2233,189 2239,183 2249,183 2251,185 2251,277.07 2253.93,280 2263.07,280 2266,277.07 2266,187 2270,183 2283,183 v2(2409,309)
  L4-SIG w3: v2@2408,312 2408,359 2416,367 2416,677 2425,686 v2(2425,766)
  L6 w3: v2(2425,766) 2425,780 2842.5,1197.5 2842.5,1364.08 2842,1364.58 2842,1418 2814,1446 2814,1748 2828,1762 2828,1784 2804,1808 2633,1808 2618,1793 v3(2618,1761.36)
P4_5: J17.2 U3.A19 U21.M5 | length 4128.3
  L1 w3: U3.A19@2582.16,1867.16 2584.02,1867.16 2591.85,1875 2734,1875 2751,1858 v3(2751,1856)
  L1 w5: v3@1020,570 1020,610 1025.95,615.94 U21.M5@1046.26,615.94 ; v2(2473,293) 2475,295 J17.2@2475,388.23
  L3-SIG w5: v2(965,360) 982,377 1118,377 1146,349 1357,349 1413,293 1733,293 1905,121 2301,121 v2(2473,293)
  L4-SIG w5: v2(965,360) 1006.89,401.89 1006.89,555.96 v3(1020.45,569.53) ; v2(2473,293) 2513,293 2578,358 2578,721 2575,724 v2(2575,759) v2@2575,761
  L6 w3: v2(2575,759) 2560,774 2560,851 2874,1165 2874,1430.46 2848,1456.46 2848,1737.51 2859,1748.51 2859,1795.97 2813.97,1841 2766,1841 v3(2751,1856)
P4_6: J17.8 U3.A18 U21.G5 | length 4212
  L1 w3: U3.A18@2562.48,1867.16 2571.9,1857.74 2698.74,1857.74 2699.28,1858.28 2703.28,1858.28 v3(2705,1860)
  L1 w5: v2(2313,317) 2325,329 J17.8@2325,388.23
  L3-SIG w5: v3(1046.26,714.37) 1059.21,701.42 1191.58,701.42 1200,693 1200,522 1243.85,478.15 1321.85,478.15 1412,388 1455,388 1487,356 1565,356 1571,362 1571,467 1574,470 1585,470 1590,465 1590,363 1597,356 1782,356 1786,360 1786,448 1790,452 1804.07,452 1807,449.07 1807,361 1812,356 1859,356 1898,317 v2(2313,317)
  L4-SIG w5: v2(2313,317) 2359,317 2394,282 2421,282 2470,331 2504,331 2564,391 2564,682 2540,706 v2(2540,754)
  L6 w3: v2(2540,754) 2540,841 2867,1168 2867,1428.97 2841,1454.97 2841,1739 2853,1751 2853,1793.49 2813.49,1833 2717,1833 2705,1845 v3(2705,1860)
P4_7: J17.6 U3.B16 U21.H5 U21.R10 | length 4202.4
  L1 w3: v4(1143,528) 1142.74,528.26 1142.74,530.74 1144.68,532.68 U21.R10@1144.68,556.89 ; U3.B16@2523.11,1847.48 2533.37,1857.74 2533.37,1878.37 2539,1884 2782,1884 v2@2796,1870
  L1 w5: v2(2350,290) 2375,315 J17.6@2375,388.23
  L3-SIG w3: 1115,527 1116,528 v4(1143,528)
  L3-SIG w5: v3(1046.26,694.68) 1115,625.94 1115,527 1115,490 1143,462 1311,462 1398,375 1449,375 1484,340 1849,340 1899,290 2297,290 2301,286 2301,272 2304,269 2315,269 2319,273 2319,285 2324,290 v2(2350,290)
  L4-SIG w3: v2@2349,291 v2(2350,290) 2389,251 2740,251 2790,301 2790,540 2843,593 2843,844 v2(2860,861)
  L6 w3: v2(2795,1870) 2796.74,1868.26 2807.74,1868.26 2871,1805 2871,1756.51 2897.5,1730.01 2897.5,1395.81 2892.5,1390.8 2892.5,1107.99 2899,1101.49 2899,900 v2(2860,861)
P5_0: U3.A16
P5_1: U3.B14
P5_2: U3.E12
P5_3: U3.B13
P5_4: R67.2 R68.2 U3.E11 | length 6021.5
  L1 w3: v3(2413,1740) 2413,1776.54 2424.68,1788.22 U3.E11@2424.68,1788.43 ; R67.2@4242,2874.31 4242,2833 v2(4243,2832) ; R68.2@4280,174.37 4280,274 4312,306 v2(4460,306)
  L3-SIG w3: v2(2429,2711) 2431.02,2711 2439.02,2719 4130,2719 v2(4243,2832)
  L4-SIG w3: v3(2413,1740) 2413,1781.58 2415.5,1784.08 2415.5,1814.01 2422,1820.51 2422,1894 2469,1941 2469,2017 2491,2039 2491,2215 2506,2230 2506,2286 2478,2314 2443,2314 2429,2328 v2(2429,2711) ; v2(4243,2832) 4243,1999 4340,1902 4340,1000 4543,797 4543,353 4495,305 4461,305 v2(4460,306)
P5_6: U3.B12
P5_7: S5.2 U3.B11 | length 2010
  L1 w3: U3.B11@2424.68,1847.48 2415,1857.16 2415,1907.51 2495.49,1988 v2(2535,1988)
  L4-SIG w3: v2(1748,2332) 1700,2332 1663,2295 1663,2125 1686,2102 1713,2102 1739,2128 v2(1758,2128) ; v2(2535,1988) 2538,1991 2570,1991 2665,2086 2665,2210 2644,2231 v2(2644,2281)
  L6 w3: S5.2@1708.3,2081 1744,2081 1757,2094 v2@1757,2129 ; v2(1748,2332) 1780,2364 2136,2364 2179,2321 2448,2321 2461,2308 2617,2308 v2(2644,2281)
P6_0: U3.A12
P6_1: R88.2 U3.E9 U22.4 | length 1653.1
  L1 w3: U3.E9@2385.32,1788.43 2385.32,1760.26 2391,1754.57 v3(2391,1754) ; U22.4@3404.75,1367.4 3406.34,1365.81 3406.34,1354.66 3420,1341 v2@3420,1329 ; U22.4@3405.31,1368.31 R88.2@3405.31,1435
  L3-SIG w3: v2(2459,1307) 3400,1307 v2(3420,1327)
  L4-SIG w3: v3(2391,1754) 2391,1734 2399,1726 2447,1726 2456,1717 2456,1689 2438,1671 2438,1625 2474,1589 2474,1500 2453,1479 2453,1313 v2(2459,1307)
P6_2: Q4.1 R22.2 U3.A11 | length 1336.9
  L1 w3: U3.A11@2424.68,1867.16 2424.68,1906.68 2487,1969 2561,1969 v2(2567,1975) ; Q4.1@3144.69,2354.57 3144.69,2356.68 3145,2357 v2(3175,2357) 3177,2357 v2@3178,2356
  L3-SIG w3: v2(2651,2429) 3103,2429 v2(3175,2357)
  L4-SIG w3: v2(2567,1975) 2675,2083 2675,2318 2651,2342 v2(2651,2429)
  L6 w3: R22.2@3144.69,2355 v2@3173,2355
P6_3: R107.1 R109.2 U3.B10 | length 3747.8
  L1 w5: R109.2@1781,772 v2(1841,772) ; R109.2@1781,773 1781,772.35 1764,755.35 1764,751 1756,751 1737,732 1737,565 1798,504 1798,359 1823,334 1823,93 v4(1796,66)
  L3-SIG w5: v2@1839,770 v2(1841,772)
  L6 w5: R107.1@542.32,364 542.32,345.32 504,307 504,189 593,100 966,100 989,77 1785,77 v4(1796,66) ; v2(1841,772) 1850,772 1868,790 1868,1031.31 2110,1273.31 2110,1432 2113,1435 2113,1445.59 2116.5,1449.09 2116.5,1504.6 2182.6,1570.7 2248.7,1570.7 2266.4,1588.4 2271.87,1588.4 2278.6,1595.13 2278.6,1600.6 2346,1668 2346,1790 2361,1805 2392,1805 2405,1818 v3(2405,1847.48)
P6_4: R108.1 R110.2 U3.E8 | length 3147.5
  L1 w5: R110.2@1827.69,721 1867,721 1877,731 v2(1877,752)
  L4-SIG w5: v4(1832,414) 1868,378 v4(1868,261)
  L6 w5: R108.1@658.68,366 831,366 911,286 985,286 1028,243 1850,243 v4(1868,261) ; v4(1832,414) 1832,612 1877,657 v2(1877,752) 1877,1029 2118,1270 2118,1428.69 2124.5,1435.19 2124.5,1501.29 2183.21,1560 2254,1560 2274.4,1580.4 2275.18,1580.4 2286.6,1591.82 2286.6,1592.6 2355,1661 2355,1777.8 v3(2365.63,1788.43)
P6_5: Q5.1 R24.2 U3.E7 | length 1818.4
  L1 w3: U3.E7@2345.95,1788.43 2345.95,1803.95 2355,1813 2370,1813 2373.08,1816.08 2373.64,1816.08 2376.56,1819 v3(2379,1819) ; Q5.1@3289.69,2529.57 3290.11,2530 3344,2530 v2(3367,2507)
  L3-SIG w3: v2(2490,2254) 2508,2272 2594.49,2272 2600.99,2265.5 2826.01,2265.5 2832.51,2272 3225,2272 3228,2275 3230.48,2275 3231.23,2274.25 3240.75,2274.25 v2(3244,2271)
  L4-SIG w3: v3(2379,1819) 2379,1892 2437.62,1950.62 2437.62,2209.62 2482,2254 v2(2490,2254) ; v2(3244,2271) 3316,2343 3378.24,2343 3380,2344.76 3380,2494 v2(3367,2507)
  L6 w3: R24.2@3289.69,2529.57 3290.11,2530 3344,2530 v2(3367,2507)
P6_6: Q6.1 R25.2 U3.E6 | length 1728.9
  L1 w3: Q6.1@3144.69,2524.57 3147.11,2527 3194,2527 v2(3214,2507)
  L3-SIG w3: v2(2425,2221) 3128,2221 v2(3142,2207)
  L4-SIG w3: v3(2326.26,1788.43) 2326.26,1811.26 2333,1818 2354,1818 2367,1831 2367,1895 2425,1953 v2(2425,2221) ; v2(3142,2207) 3142,2495 3154,2507 v2(3214,2507)
  L6 w3: R25.2@3144.69,2525 3196,2525 v2(3214,2507)
P6_7: U3.A9 U17.6 U18.6 | length 5512.2
  L1 w3: U3.A9@2385.32,1867.16 2385.32,1896.32 2518,2029 2584,2029 2595,2040 2595,2052.49 2595.5,2052.99 2595.5,2069.5 2611,2085 3032,2085 v2(3046,2071) ; U17.6@4374,2984 4374,3009 4384,3019 4433.93,3019 v3(4463.45,3048.53) ; U18.6@4375,180 4375,200 4394,219 4442,219 v3@4458,235
  L3-SIG w3: v2(3046,2071) 3235,2071 3265,2101 4101,2101 4119,2119 v2(4119,2207) ; v3@4244,833 4245.48,831.53 v3(4410.45,831.53)
  L4-SIG w3: v3(4244.45,832.53) 4244.45,1890.55 4119,2016 v2(4119,2207) 4119,2316 4185,2382 4185,2936 4258.66,3009.66 4423.66,3009.66 v3@4463,3049 ; v3@4410,832 4410,282.98 v3(4458.45,234.53)
P7_0: U3.B8
P7_1: U3.B3
P7_4: Q2.1 R18.2 U3.T1 | length 1922
  L1 w3: v2(2112,1578) 2118.11,1571.89 U3.T1@2227.84,1571.89 ; Q2.1@2834.69,2529.57 2839.09,2525.17 2839.09,2511.11 2848,2502.2 v2(2848,2502)
  L3-SIG w3: v2(2305,2201) 2321,2185 v2(2842,2185)
  L4-SIG w3: v2(2842,2185) 2842,2189.26 2855,2202.26 2855,2491.74 2848,2498.74 v2(2848,2502)
  L6 w3: v2(2112,1578) 2112,1699 2087,1724 2056,1724 2049,1731 2017,1731 1997,1751 1997,1902 2076,1981 2101,1981 2113,1993 2113,2034 2164.5,2085.5 2164.5,2088.89 2218.93,2143.32 2221.82,2143.32 2279.51,2201 v2(2305,2201) ; R18.2@2834.69,2530 2834.69,2512.32 2845,2502 v2(2848,2502)
P8_1: U3.C2 U11.31 | length 1389
  L1 w3: U11.31@1078.74,2089.37 1114.63,2089.37 v2(1116,2088) ; v2(2135,1821) 2135,1823.24 2136.76,1825 2196,1825 2208.22,1837.22 2233.78,1837.22 2241.9,1829.1 2246.21,1829.1 U3.C2@2247.52,1827.8
  L3-SIG w3: v2(1116,2088) 1125,2097 1394,2097 1421,2070 1975,2070 2023,2022 v2(2087,2022)
  L4-SIG w3: v2(2087,2022) 2087,1969 2135,1921 v2(2135,1821)
P8_2: U3.C3 U11.32 | length 1391.8
  L1 w3: U11.32@1078.74,2105.12 1110.12,2105.12 1117,2112 v2(1117,2132)
  L3-SIG w3: v2(1117,2132) 1393,2132 1445,2080 v2(2108,2080)
  L4-SIG w3: v2(2108,2080) 2108,2006.68 2267.2,1847.48 v3(2267.2,1827.8)
P8_3: U3.A7 U11.29 | length 2126.2
  L1 w3: U11.29@1078.74,2057.87 1103.85,2057.87 1112,2049.73 v2(1112,2048) ; U3.A7@2345.95,1867.16 2345.95,1878.95 2527,2060 v2(2553,2060)
  L3-SIG w3: v2(1092,2268) 1118,2242 2133,2242 2154,2221 2181,2221 2187,2227 2355,2227 v2(2379,2203)
  L4-SIG w3: v2(1092,2268) 1092,2229 1085,2222 1085,2062 1099.26,2047.74 1111.74,2047.74 v2(1112,2048)
  L6 w3: v2(2379,2203) 2383,2203 2420,2166 2447,2166 v2(2553,2060)
P8_4: U3.B4 U16.4 | length 1523.1
  L1 w3: v2(2107,1093) 2107,1088.4 2110.47,1084.93 U16.4@2110.47,1060.87 ; U3.B4@2286.89,1847.48 2286.89,1849.33 2289.35,1851.79 2289.35,1852.35 2295,1858 2295,1861.95 2296.31,1863.26 2296.31,1912.31 2302,1918 2302,2025 v2(2299,2028)
  L3-SIG w3: v2(1998,1363) 1998,1202 v2(2107,1093) ; v2(2044,2040) 2048.51,2040 2056.51,2048 2230,2048 2250,2028 v2(2299,2028)
  L6 w3: v2(1998,1363) 1998,1461.49 2009.5,1472.99 2009.5,1519 1988,1540.5 1988,1907 2009.5,1928.5 2009.5,2015.5 2020.12,2026.12 2030.12,2026.12 v2(2044,2040)
P8_5: U3.H1 U14.4 | length 1196.9
  L1 w3: v2(2027,1712) 2027,1716.24 2028.76,1718 2092,1718 2108,1702 2175,1702 2202.37,1729.37 U3.H1@2227.84,1729.37 ; v2(2372,1142) 2385.47,1128.53 U14.4@2385.47,1050.77
  L3-SIG w3: v2(2028,1346) 2028,1207 2093,1142 v2(2372,1142)
  L6 w3: v2(2027,1712) 2027,1347 v2(2028,1346)
P8_6: U3.J2 U13.6 U15.6 | length 5682.5
  L1 w3: v2(2050,1690) 2065,1705 2094,1705 2104,1695 2178,1695 2202.11,1719.11 2238.1,1719.11 U3.J2@2247.52,1709.68
  L1 w5: v2(325,70) 427,70 450,93 U15.6@450,110 ; v2@448,2861 450,2863 U13.6@450,2915
  L3-SIG w3: v2(506,2423) 531,2398 1623.49,2398 1623.99,2397.5 1991.5,2397.5 v2(2050,2339)
  L4-SIG w3: v2(2050,1690) 2018.5,1690 2006,1702.5 2006,2130 2050,2174 v2(2050,2339)
  L4-SIG w5: v2(325,70) 420,70 452,102 452,203.08 466.5,217.58 466.5,230.42 434,262.92 434,915.42 454.5,935.92 454.5,1316.42 452,1318.92 452,2251 506,2305 v2(506,2423) 506,2739 448,2797 v2(448,2858)
P8_7: U3.J1 U13.1 U15.1 | length 5311.7
  L1 w3: v2(2086,1687) 2182,1687 2204.68,1709.68 U3.J1@2227.84,1709.68
  L1 w5: U15.1@482.28,180.87 482.28,313.28 v2(505,336) ; U13.1@482.28,2985.87 509.13,2985.87 v2@510,2985
  L3-SIG w3: v2(530,2371) 548,2389 1549,2389 1556.82,2381.18 1985.82,2381.18 2033,2334 v2(2033,2309)
  L4-SIG w3: v2(2033,2309) 2037,2305 2037,2175 1995,2133 1995,1693 2017.68,1670.32 2069.32,1670.32 v2(2086,1687)
  L4-SIG w5: v2(505,336) 522,353 522,1496 530,1504 v2(530,2371) 530,2871 511,2890 v2(511,2985)
P9_0: R64.2 R65.2 U3.K2 | length 5045.7
  L1 w5: R65.2@530,279.69 530,308 v2(537,315) ; R64.2@550,2910.31 550,2886 554,2882 v2@554,2860
  L3-SIG w3: v2(552,2334) 552,2348 580,2376 1089,2376 1119,2346 1573,2346 1594,2367 1878,2367 v2(1927,2318)
  L4-SIG w3: v2(1927,2318) 1927,2218 1983,2162 1983,1679 2001,1661 2107,1661 2155.68,1709.68 2227.84,1709.68 v3(2247.52,1690)
  L4-SIG w5: v2(537,315) 537,1474 552,1489 552,2857 v2(554,2859)
P9_2: J10.15 J12.15 U3.G5 | length 4070.1
  L1 w3: U3.G5@2306.57,1749.05 2333.95,1749.05 v3(2334,1749) ; J10.15@4400,456.26 4429.74,456.26 4452,434 4568.74,434 4574.74,440 v2(4579,440)
  L3-SIG w3: v2(2255,1114) 2413,1114 2432,1133 3415,1133 3635,913 v1(4571,913)
  L4-SIG w3: v2(2255,1114) 2255,1315 2292,1352 2292,1385 2300,1393 2300,1428.6 2300,1429.64 2300,1476 2320,1496 2360,1496 2423,1559 2423,1578 2384,1617 2367,1617 2336,1648 2336,1742.74 2335.72,1743.02 2335.72,1747.28 v3(2334,1749) ; v1(4571,913) 4569,911 4569,685 4579,675 v2(4579,440)
  L6 w3: J12.15@4400,647.48 4400.53,648.01 4411.01,648.01 4422,659 4443,659 4468,684 v2(4569,684)
P9_3: J10.20 J12.20 U3.H5 | length 4123
  L1 w3: U3.H5@2306.57,1729.37 2318.63,1729.37 2323.28,1724.72 2323.28,1720.72 v3(2325,1719) ; v2(3784,549) 3784,461 3870,375 4198,375 4279.26,456.26 J10.20@4314.17,456.26
  L4-SIG w3: v2(2256,627) 2256,885 2270,899 2270,1019.51 2257,1032.51 2257,1079 2234,1102 2234,1303 2280,1349 2280,1394 2294,1408 2294,1447 2291,1450 2291,1476 2317,1502 2349.96,1502 2356.45,1508.49 2398.96,1551 2405,1551 2416,1562 2416,1572 2395.82,1592.18 2395.82,1595.92 2389.66,1602.07 2385.93,1602.07 2381,1607 2365,1607 2325,1647 v3(2325,1719) ; v2(3784,549) 3859,549 3920,610 4022,610 4041,629 4273.98,629 4281.98,637 v2(4284,637)
  L6 w3: v2(2256,627) 2320,563 2684,563 2712,535 2787,535 2801,549 2969,549 2975,555 3081,555 3087,549 v2(3784,549) ; v2(4284,637) 4294.48,647.48 J12.20@4314.17,647.48
P9_4: R91.1 R92.1 U3.J5 | length 1624.8
  L1 w4.72: v2(2279,1753) 2279,1737.26 U3.J5@2306.57,1709.68 ; R92.1@3287,2237.32 3288.97,2237.32 3297.44,2228.85 3297.44,2226.88 3303,2221.31 3303,2200 v2@3302,2199 ; v2(3303,2198) 3333.32,2198 R91.1@3339.31,2192 ; R91.1@3336.31,2196.68 R91.1@3340.16,2192.84
  L3-SIG w4.72: v2(2463,2203) 3105,2203 3123,2185 3144,2185 3190,2139 3286,2139 3303,2156 v2(3303,2198)
  L4-SIG w4.72: v2(2279,1753) 2291,1765 2334,1765 2346,1777 2346,1788.65 2364.99,1807.64 2386.11,1807.64 2390.36,1811.89 2390.36,1888.36 2448,1946 2448,2188 v2(2463,2203)
P10_5: U3.N5
P10_6: U3.P5
P11_0: U3.P2 U11.30 | length 1745.5
  L1 w3: U11.30@1078.74,2073.62 1105.38,2073.62 1115,2064 1178,2064 v2(1179,2065) ; v2(1595,1541) 1629,1507 1920,1507 1939,1526 1939,1592 1968,1621 2235,1621 2242.47,1613.53 2243.4,1613.53 2245.67,1611.26 U3.P2@2247.52,1611.26
  L3-SIG w3: v2(1179,2065) 1252,2065 1320,1997 v2(1568,1997)
  L4-SIG w3: v2(1568,1997) 1568,1735 1595,1708 v2(1595,1541)
P11_1: U3.R1
P11_2: U3.R2
P11_3: U3.R5
P11_4: U3.K8
P11_5: U3.J9
P11_6: U3.R6
P11_7: U3.L9
P12_0: Q3.1 R19.2 U3.F19 | length 1285.6
  L1 w3: Q3.1@2649.69,2529.57 2649.26,2530 2693,2530 2714,2509 2714,2501.52 2712.24,2499.76 2703.26,2499.76 v2(2700.5,2497)
  L3-SIG w3: v2(2700.5,2497) 2719.5,2478 v2(2925,2478)
  L4-SIG w3: v3(2583,1769) 2583,1786 2613,1816 2613,1819.15 2613.5,1819.65 2613.5,1834.5 2687,1908 2687,1950 2878,2141 2878,2290 2933,2345 2933,2390 2921,2402 2921,2467.74 2921.75,2468.49 2921.75,2474.75 v2(2925,2478)
  L6 w3: R19.2@2649.69,2529.57 2693.43,2529.57 2714,2509 2714,2501.52 2712.24,2499.76 2703.26,2499.76 v2(2700.5,2497)
P12_1: J15.10 U3.E18 | length 3045.8
  L1 w3: v3@2538,1772 2538.42,1772.42 2545.42,1772.42 2561.43,1788.43 U3.E18@2562.48,1788.43
  L4-SIG w3: v3(2538,1771) 2538,1840 2549,1851 2611,1851 2671,1911 2671,1956 2862,2147 2862,2439 2872,2449 2872,2755 v2(2799,2828)
  L6 w3: J15.10@1128,2951 1175,2904 1313,2904 1364,2853 2001,2853 2063,2791 2762,2791 v2(2799,2828)
P12_2: J15.9 U3.E15 | length 2852
  L1 w3: U3.E15@2503.43,1788.43 2513,1798 v3(2513,1810)
  L4-SIG w3: v3(2513,1810) 2514.72,1811.72 2514.72,1815.98 2515,1816.26 2515,1862 2529,1876 2592,1876 2613,1897 2613,1933 2778,2098 2778,2316 2786,2324 2786,2355 2761,2380 2761,2609 2826,2674 v2(2826,2685)
  L6 w3: J15.9@1131,2852 1308,2852 1376,2784 1986,2784 1996,2774 2737,2774 v2(2826,2685)
P12_3: Q1.1 R15.2 U3.D18 | length 1021
  L1 w3: U3.D18@2562.48,1808.11 2572.74,1818.37 2586.07,1818.37 2591.69,1824 v3(2603,1824) ; Q1.1@2654.69,2370 v2(2684,2370) 2686,2370 v2@2687,2369
  L3-SIG w3: v2(2684,2370) 2686,2368 2778,2368 2779,2367 2801,2367 2806,2372 v2(2914,2372)
  L4-SIG w3: v3(2603,1824) 2603,1833 2680,1910 2680,1954 2871,2145 2871,2329 v2(2914,2372)
  L6 w3: R15.2@2654.37,2370 v2(2684,2370) v2@2685,2369
P12_4: U3.F5 U8.3 | length 973.7
  L1 w3: v4(1662,2055) 1945,2055 2026,1974 2026,1856 2093,1789 2093,1778 2129,1742 2166,1742 2203,1779 2279,1779 2289.26,1768.74 U3.F5@2306.57,1768.74 ; v4@1662,2056.76 1662,2076 1675,2089 U8.3@1675,2155
  L6 w3: v4@1661.5,2055.5 v4(1662,2055)
P12_5: U3.A10 U8.4 | length 1687.2
  L1 w3: v2@1695,2121 U8.4@1695,2163.82 ; U3.A10@2405,1867.16 2405,1906 2510,2011 v2(2562,2011)
  L4-SIG w3: v2(1694,2123) 1695,2124 1695,2270 1718,2293 v2(1779,2293) ; v2(2562,2011) 2652,2101 2652,2195 2601,2246 v2(2601,2286)
  L6 w3: v2(1779,2293) 2104,2293 2105,2294 2169,2294 2183,2280 2450,2280 2456,2286 v2(2601,2286)
P12_6: U3.E5 U8.5 | length 1075.6
  L1 w3: U8.5@1715,2158 1715,2111 1726,2100 1824,2100 v2(1838,2114) ; v2(2149,1934) 2123,1934 2111,1946 2111,1973 2119,1981 2154,1981 2159,1976 2190,1976 2227,1939 2246,1939 2257.78,1927.22 2257.78,1861.22 2262,1857 2273,1857 2277,1853 2277,1838 2284,1831 2293,1831 2306.57,1817.43 U3.E5@2306.57,1788.43
  L3-SIG w3: v2(1838,1959) 1845,1966 1941,1966 1946,1961 2068,1961 2095,1934 v2(2149,1934)
  L4-SIG w3: v2(1838,1959) v2(1838,2114)
P12_7: U3.D2 U8.2 | length 1037.4
  L1 w3: U8.2@1655.63,2163.82 1655.63,2103.37 v2(1656,2103) ; v2(2168,1810) 2170.73,1810 2178.26,1817.53 2238.1,1817.53 U3.D2@2247.52,1808.11
  L3-SIG w3: v2(1656,2103) 1663,2096 2083,2096 2103,2116 v2(2116,2116)
  L4-SIG w3: v2(2116,2116) 2103,2116 2063,2076 2063,2001 2072,1992 2072,1961 2111,1922 2111,1812 2122,1801 2151,1801 2154.75,1804.75 2158.15,1804.75 2163.4,1810 v2(2168,1810)
P13_0: R93.2 U3.G18 | length 2701.8
  L1 w3: R93.2@1473,2739 1514,2739 1529,2724 v2(1529,2652) ; v3(2527,1689) 2528,1688 2545,1688 2551,1694 2551,1742 2556.75,1747.75 2561.17,1747.75 U3.G18@2562.48,1749.05
  L4-SIG w3: v3(2527,1689) 2514,1702 2514,1796 2523,1805 2523,1805.15 2523.5,1805.65 2523.5,1856.5 2534,1867 2601,1867 2621,1887 2621,1930 2800,2109 2800,2365 2804,2369 2804,2398 2782,2420 2782,2427 2773,2436 2773,2607 2785,2619 2812,2619 v2(2821,2628)
  L6 w3: v2(1529,2652) 1530,2651 1801,2651 1820,2670 2147,2670 2157,2680 2398,2680 2426,2652 2797,2652 v2(2821,2628)
P13_1: U3.G15 U9.2 | length 1587.4
  L1 w3: U9.2@2319,2677 2321,2675 2417,2675 2437,2655 2757,2655 v2(2784,2682) ; v3(2476.5,1832) 2476.5,1809.2 2478,1807.7 2478,1799 2474,1795 2474,1780 2487.5,1766.5 2487.5,1764.98 U3.G15@2503.43,1749.05
  L4-SIG w3: v3(2476.5,1832) 2476,1832.5 2476,1844 2515,1883 2561,1883 2575,1897 2575,1919 2745,2089 2745,2631 2784,2670 v2(2784,2682)
P13_2: R45.1 U3.F15 U9.5 | length 1544.8
  L1 w3: U9.5@2321.18,2734.68 2362.4,2734.68 2380.03,2752.32 R45.1@2382,2752.32 2457.68,2752.32 v4(2513,2697) ; U3.F15@2503.43,1768.74 2493.16,1779 2493.16,1854.16 2496.74,1857.74 2507.74,1857.74 2513.69,1863.69 2513.69,1871.69 2514,1872 2514,1879 2526,1891 2584.98,1891 2586.74,1892.76 2586.74,1894.14 2586.75,1900.75 v2(2590,1904)
  L3-SIG w3: v2(2535,2396) 2595,2396 2645,2346 v2(2767,2346)
  L4-SIG w3: v4(2513,2697) 2513,2650 2484,2621 2484,2493 2535,2442 v2(2535,2396) ; v2(2590,1904) 2590,1923 2767,2100 v2(2767,2346)
P13_3: U3.E13 U9.4 | length 1509.6
  L1 w3: U9.4@2321.18,2715 2402,2715 2449.5,2667.5 2736.5,2667.5 v2(2751,2682) ; U3.E13@2464.05,1788.43 2464.05,1797.05 2465.78,1798.78 2465.78,1801.63 v3(2467.5,1803.35)
  L4-SIG w3: v3(2467.5,1803.35) 2466,1804.85 2466,1868 2488,1890 2557,1890 2568,1901 2568,1922 2737,2091 2737,2668 v2(2751,2682)
P13_4: U3.E14
P13_5: U3.A17
P13_6: U3.B15
P13_7: U3.A15
P14_0: U3.B9
P14_1: U3.H2
P14_2: U3.G1 U11.1 | length 1488.4
  L1 w3: U11.1@1055.12,2128.74 1063.74,2128.74 v2(1108,2173) ; v2(1347,2053) 1542,2053 1572,2023 1931,2023 1995,1959 1995,1805 2072,1728 2093,1728 2110,1711 2171,1711 2209.05,1749.05 U3.G1@2227.84,1749.05
  L6 w3: v2(1108,2173) 1171.48,2173 1291.48,2053 v2(1347,2053)
P14_3: U3.R7
P14_4: U3.R8
P14_5: U3.L11
P14_6: U3.K12
P14_7: U3.L12
P15_0: SW2.1 U3.V2 | length 2285.2
  L1 w3: v2(1820,1082) 1863,1082 1880,1099 1880,1402 1994.2,1516.2 2107.2,1516.2 2133,1542 2238.04,1542 U3.V2@2247.52,1532.52 ; v2(3096,934) 3111.3,918.7 SW2.1@3192.48,918.7
  L3-SIG w3: v2(1820,1082) 1977,925 2191,925 2218,898 2629,898 2684,953 2754,953 2772,935 3095,935 v2(3096,934)
P15_1: SW2.4 U3.W2 | length 2153.5
  L1 w3: v2(1786,1018) 1851,1018 1907,1074 1907,1394 v2(1989,1476) ; v2(2143,1465) 2143,1497 2149,1503 2237.68,1503 U3.W2@2247.52,1512.84 2247.68,1513 U3.W2@2248,1513 ; v2(2878,818) 2878,909 SW2.4@2880,911
  L3-SIG w3: v2(1786,1018) 1938,866 2178,866 2197,847 2589,847 v2(2600,836) ; v2(1989,1476) v2@1991,1478 ; v2@2142,1464 v2(2143,1465)
  L3-SIG w5: v2@1991,1478 2103,1478 2117,1464 v2@2142,1464
  L6 w3: v2(2600,836) 2647,836 2665,818 v2(2878,818)
P15_2: SW2.3 U3.U2 | length 2258.1
  L1 w3: v2(1836,1117) 1836,1386 1983,1533 2096,1533 2125,1562 2237.72,1562 U3.U2@2247.52,1552.2 ; v2(3112,1027) 3116.6,1027 3120.51,1030.91 SW2.3@3192.48,1030.91
  L3-SIG w3: v2(1836,1117) 2012,941 2466,941 2487,920 2607,920 2628,941 2651,941 2675,965 2758,965 2778,945 2883,945 2941,1003 3088,1003 v2(3112,1027)
P15_3: SW2.6 U3.V1 | length 2039.7
  L1 w3: v2(1812,1047) 1850,1047 1893,1090 1893,1403 1998,1508 2110,1508 2137,1535 2217,1535 2219.48,1532.52 U3.V1@2227.84,1532.52 ; v2@2808,1030 2876.61,1030 SW2.6@2877.52,1030.91
  L3-SIG w3: v2(1812,1047) 1975,884 2189,884 2211,862 2603,862 2622,881 v2(2646.6,881)
  L6 w3: v2(2646.6,881) 2646.6,921.6 2756,1031 v2(2809,1031)
P15_4: SW2.2 U3.V3 | length 2690.7
  L1 w3: v2(1781,985) 1839,985 1920,1066 1920,1333 2045,1458 v2(2095,1458) ; v2(2195,1450) 2195,1472 2208.5,1485.5 2253.5,1485.5 2276,1508 ; U3.V3@2267.2,1532.52 2268.51,1531.21 2268.51,1527.49 2277,1519 2277,1508 ; SW2.2@3194,978 3248,978 3260,966 3260,835.02 v2(3251,826)
  L3-SIG w3: v2(1781,985) 1919,847 2177,847 2223,801 v2(2587,801)
  L4-SIG w3: v2(2095,1458) 2107,1446 2146.7,1446 2150.7,1450 v2(2195,1450)
  L6 w3: v2(2587,801) 3226,801 v2(3251,826)
PA_OUT_L: C59.1 FB12.1 U11.13 | length 460.9
  L1 w6: FB12.1@626,2180 C59.1@670,2180 670,2040 692,2018 840,2018 872,2050 895,2050 901.94,2043.06 920.32,2043.06 U11.13@921.26,2042.13
PA_OUT_R: C58.1 FB11.1 U11.15 | length 1214.3
  L1 w6: FB11.1@320,2541 321,2540 C58.1@472.28,2540 ; v2(409,2006) 853,2006 857.63,2010.63 U11.15@921.26,2010.63
  L3-SIG w6: v2(379,2541) 379,2284 409,2254 v2(409,2006)
PMU_AMUX: TP23.1 U3.M18 | length 595.3
  L1 w3: U3.M18@2562.48,1650.63 2571.9,1660.05 2586.07,1660.05 2613,1633.12 v2(2613,1627)
  L4-SIG w3: v2(2613,1627) 2687.51,1627 2895.51,1419 3042,1419 TP23.1@3048,1425
PMU_AMUX_J: TP56.1 U21.M18 | length 113.2
  L6 w8: v3(1302.16,615.94) 1345.95,615.94 TP56.1@1395,665
POR_N: R39.1 SW1.1 U3.U18 U21.L5 | length 3827.3
  L1 w3: U3.U18@2562.48,1552.2 2572.28,1562 2646,1562 2658,1550 2852,1550 v2(2869,1567)
  L1 w5: v2(2685,348) 2687.31,350.32 R39.1@2725,350.32 2727.05,348.27 SW1.1@2727.05,200
  L3-SIG w5: v3(1046.26,635.63) 1046.26,625.74 1094,578 1094,435 1167,362 1364,362 1415,311 1751,311 1907,155 2294,155 2457,318 2655,318 v2(2685,348)
  L4-SIG w3: v2@2684,350 2684,455 2811,582 v2(2811,848)
  L6 w3: v2(2811,848) 2840,877 2840,890 2883,933 2883,1449 2869,1463 v2(2869,1567)
POR_N_J: R78.1 SW3.3 U21.U18 U23.18 | length 2027.3
  L1 w3: 1202,359 1208,365 1208,445 1226,463 1226,464 1233,471 1233,507 1256,530 1289.68,530 U21.U18@1302.16,517.52
  L1 w5: v4(449,512) 452.52,512 461.15,503.37 U23.18@499.86,503.37 ; v4(1175,306) 1175,332 1202,359 ; v4@1175.5,306.5 1237,245 1589,245 SW3.3@1664,170 1665.32,171.32 R78.1@1665.32,420
  L3-SIG w5: v4(449,512) 469.74,491.26 491.74,491.26 514,469 514,407 562,359 650,359 705,304 v4(788,304) ; v4(854,300) 855,301 1016,301 1040,325 1156,325 v4(1175,306)
  L4-SIG w5: v4(788,304) 792,300 v4(854,300)
PWR_V_SUM: C9.2 D7.1 D8.1 S3.1 | length 1479.6
  L1 w25: D7.1@455,1785 556,1785 737,1604 737,1510 732,1505 v2(732,1457) 761,1457 770,1466 C9.2@770,1487.28 ; D8.1@578,960 v2@729,960
  L4-SIG w25: v2(732,961) v2(732,1457)
  L6 w25: v2@733,1458 733,1372 764,1341 841,1341 859.7,1359.7 S3.1@859.7,1390
SEU_RXD: J15.2 S8.1 | length 467.7
  L1 w5: J15.2@737,2953 680,2953 645,2918 645,2789 679,2755 v2(818,2755)
  L6 w5: v2(818,2755) 819,2756 820,2756 S8.1@820,2713.3
SEU_TXD: J15.1 S9.1 | length 143.8
  L6 w5: S9.1@725,2708.3 725,2845 J15.1@730,2850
